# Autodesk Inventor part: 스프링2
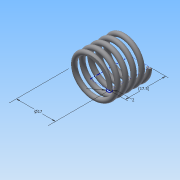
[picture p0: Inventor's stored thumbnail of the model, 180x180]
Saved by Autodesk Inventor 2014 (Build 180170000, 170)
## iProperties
Created: 2016-01
Part Number: 스프링2
Material: 강철, 탄소
Document SubType Name: Modeling
Designer: Administrator
Density: 7.87 g/cm^3
Appearance: 반연마
Mass: 6.44159 g
Surface Area: 16.7002 cm^2
Volume: 0.818499 cm^3
Author: Administrator
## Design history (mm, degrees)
sketch "스케치1"
  geometry: L1 (0, 0)-(8.5, 0); L2 (8.5, 0)-(8.5, 17.5); L3 (8.5, 17.5)-(0, 17.5); L4 (0, 17.5)-(0, 0); C1 r 1 at (8.5, 0)
  constraints: 8 end point, 2 parallel, 1 centre point, 1 coincident, 1 horizontal, 1 perpendicular
  dimensions: "d0" = 17 diameter of L2 L4; "d1" = 17.5 distance of L1.end L2.end (derived); "d2" = 2 diameter of C1
feature "코일1" sketch "스케치1" pitch "d3" = 10; turns "d5" = 5; dims "d4" = 17.5 (= d1), "d6" = 0, angle "d7" = 90 deg, angle "d8" = 90 deg, "d9" = 0, "d10" = 0
node "작업 평면2"
sketch "스케치2"
  geometry: L1 (-7.5, 0)-(-9.5, 0) reference; 1 further point
  constraints: 1 horizontal alignment
extrude "돌출1" cut sketch "스케치2" distance "d13" = 10; taper "d14" = 0 deg
node "작업 평면3"
sketch "스케치3"
  geometry: L1 (-9.5, 0)-(-7.5, 0) reference; 1 further point
  constraints: 1 horizontal alignment
extrude "돌출2" cut sketch "스케치3" distance "d16" = 10; taper "d17" = 0 deg
node "솔리드1"
node "절단 모서리 투영1"
node "절단 모서리 투영2"
other parameters: "d12" = 0, "d15" = 17.5 (= d1)
